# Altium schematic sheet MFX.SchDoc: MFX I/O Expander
size A4; Date: Not used; ApprovedBy: Not used; CheckedBy: Not used; Author: Not used; CompanyName: STMicroelectronics; DrawnBy: Not used; Engineer: Not used; Organization: Not used; Address1: Not used; Address2: Not used; Address3: Not used; Address4: Not used; DocumentNumber: Not used; Revision: Not used; SheetNumber: 18; SheetTotal: 23
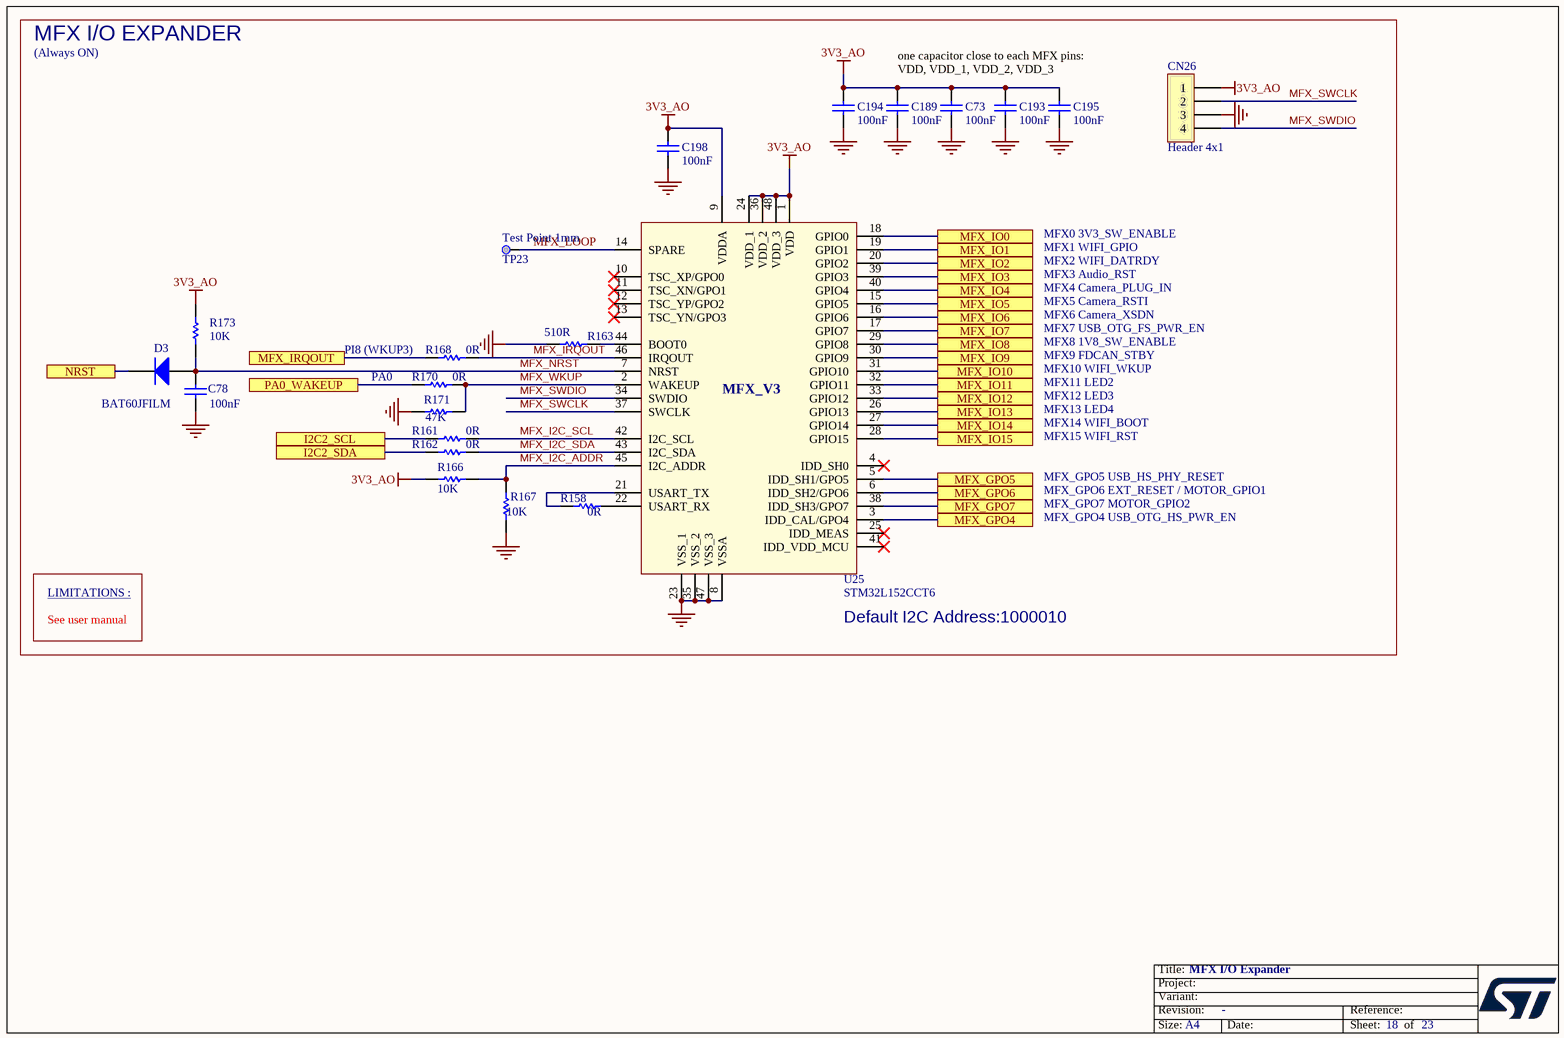
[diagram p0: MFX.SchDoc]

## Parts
C73  value 100nF  [C0402]  (hidden comment: Capacitor)
C78  value 100nF  [C0402]  (hidden comment: Capacitor)
C189  value 100nF  [C0402]  (hidden comment: Capacitor)
C193  value 100nF  [C0402]  (hidden comment: Capacitor)
C194  value 100nF  [C0402]  (hidden comment: Capacitor)
C195  value 100nF  [C0402]  (hidden comment: Capacitor)
C198  value 100nF  [C0402]  (hidden comment: Capacitor)
CN26  Header 4x1  [CON_SAMTEC_TSW-104-07-G-S]
D3  BAT60JFILM  [DIO_SOD323]
R158  value 0R  [R0603]  (hidden comment: Resistor)
R161  value 0R  [R0402]  (hidden comment: Resistor)
R162  value 0R  [R0402]  (hidden comment: Resistor)
R163  value 510R  [R0402]  (hidden comment: Resistor)
R166  value 10K  [R0402]  (hidden comment: Resistor)
R167  value 10K  [R0402]  (hidden comment: Resistor)
R168  value 0R  [R0603]  (hidden comment: Resistor)
R170  value 0R  [R0603]  (hidden comment: Resistor)
R171  value 47K  [R0402]  (hidden comment: Resistor)
R173  value 10K  [R0402]  (hidden comment: Resistor)
TP23  value Test Point 1mm  [TP_SMD_1MM]  (hidden comment: Test Point)  (no BOM)
U25  STM32L152CCT6  [ICC_LQFP48_7X7_P050]

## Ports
I2C2_SCL, I2C2_SDA, MFX_GPO4, MFX_GPO5, MFX_GPO6, MFX_GPO7, MFX_IO0, MFX_IO1, MFX_IO2, MFX_IO3, MFX_IO4, MFX_IO5, MFX_IO6, MFX_IO7, MFX_IO8, MFX_IO9, MFX_IO10, MFX_IO11, MFX_IO12, MFX_IO13, MFX_IO14, MFX_IO15, MFX_IRQOUT, NRST, PA0_WAKEUP

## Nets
3V3_AO: C73.1 C189.2 C193.2 C194.2 C195.2 C198.2 CN26.1 R166.1 R173.2 U25.1(VDD) U25.9(VDDA) U25.24(VDD_1) U25.36(VDD_2) U25.48(VDD_3)
GND: C73.2 C78.1 C189.1 C193.1 C194.1 C195.1 C198.1 CN26.3 R163.2 R167.2 R171.1 U25.8(VSSA) U25.23(VSS_1) U25.35(VSS_2) U25.47(VSS_3)
I2C2_SCL: R161.1 ; port I2C2_SCL
I2C2_SDA: R162.1 ; port I2C2_SDA
MFX_GPO4: U25.3(IDD_CAL/GPO4) ; port MFX_GPO4
MFX_GPO5: U25.5(IDD_SH1/GPO5) ; port MFX_GPO5
MFX_GPO6: U25.6(IDD_SH2/GPO6) ; port MFX_GPO6
MFX_GPO7: U25.38(IDD_SH3/GPO7) ; port MFX_GPO7
MFX_I2C_ADDR: R166.2 R167.1 U25.45(I2C_ADDR)
MFX_I2C_SCL: R161.2 U25.42(I2C_SCL)
MFX_I2C_SDA: R162.2 U25.43(I2C_SDA)
MFX_IO0: U25.18(GPIO0) ; port MFX_IO0
MFX_IO1: U25.19(GPIO1) ; port MFX_IO1
MFX_IO2: U25.20(GPIO2) ; port MFX_IO2
MFX_IO3: U25.39(GPIO3) ; port MFX_IO3
MFX_IO4: U25.40(GPIO4) ; port MFX_IO4
MFX_IO5: U25.15(GPIO5) ; port MFX_IO5
MFX_IO6: U25.16(GPIO6) ; port MFX_IO6
MFX_IO7: U25.17(GPIO7) ; port MFX_IO7
MFX_IO8: U25.29(GPIO8) ; port MFX_IO8
MFX_IO9: U25.30(GPIO9) ; port MFX_IO9
MFX_IO10: U25.31(GPIO10) ; port MFX_IO10
MFX_IO11: U25.32(GPIO11) ; port MFX_IO11
MFX_IO12: U25.33(GPIO12) ; port MFX_IO12
MFX_IO13: U25.26(GPIO13) ; port MFX_IO13
MFX_IO14: U25.27(GPIO14) ; port MFX_IO14
MFX_IO15: U25.28(GPIO15) ; port MFX_IO15
MFX_IRQOUT: R168.2 U25.46(IRQOUT)
MFX_IRQOUT: R168.1 ; port MFX_IRQOUT  [a separate net that carries the same name]
MFX_LOOP: TP23.1 U25.14(SPARE)
MFX_NRST: C78.2 D3.1(A) R173.1 U25.7(NRST)
MFX_SWCLK: CN26.2 U25.37(SWCLK)
MFX_SWDIO: CN26.4 U25.34(SWDIO)
MFX_WKUP: R170.1 R171.2 U25.2(WAKEUP)
NRST: D3.2(K) ; port NRST
PA0_WAKEUP: R170.2 ; port PA0_WAKEUP
NetR158_1: R158.1 U25.21(USART_TX)
NetR158_2: R158.2 U25.22(USART_RX)
NetR163_1: R163.1 U25.44(BOOT0)

Not connected (* = marked no-connect by the designer): U25 4(IDD_SH0)* 10(TSC_XP/GPO0)* 11(TSC_XN/GPO1)* 12(TSC_YP/GPO2)* 13(TSC_YN/GPO3)* 25(IDD_MEAS)* 41(IDD_VDD_MCU)*

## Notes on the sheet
- MFX I/O EXPANDER
- (Always ON)
- one capacitor close to each MFX pins: VDD, VDD_1, VDD_2, VDD_3
- PI8 (WKUP3)
- PA0
- MFX0	3V3_SW_ENABLE
  MFX1	WIFI_GPIO
  MFX2	WIFI_DATRDY
  MFX3	Audio_RST
  MFX4	Camera_PLUG_IN
  MFX5	Camera_RSTI
  MFX6	Camera_XSDN
  MFX7	USB_OTG_FS_PWR_EN
  MFX8	1V8_SW_ENABLE
  MFX9	FDCAN_STBY
  MFX10	WIFI_WKUP
  MFX11	LED2
  MFX12	LED3
  MFX13	LED4
  MFX14	WIFI_BOOT
  MFX15	WIFI_RST
- MFX_GPO5	USB_HS_PHY_RESET
  MFX_GPO6	EXT_RESET / MOTOR_GPIO1
  MFX_GPO7	MOTOR_GPIO2
  MFX_GPO4	USB_OTG_HS_PWR_EN
- LIMITATIONS :
- See user manual
- (near U25) Default I2C Address:1000010

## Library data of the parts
C73 C78 C189 C193-C195 C198 = MCD-00006: Capacitor, MLCC, 100nF, 16V, X7R, 10%, 0402, T=0.5mm; Manufacturer_Part_Number: CC0402KRX7R7BB104; Manufacturer: YAGEO; Alternate_Manufacturer_Part_Number: GCM155R71C104KA55D; Alternate_Manufacturer: MURATA; Part_Preference: Recommended; Partial_Alternate_Internal_Part_Number: MCD-03299; Provided_By: SUBCO; ECCN_US: EAR99; ECCN_EU: NEC; Component_Country_Of_Origin: China; ID: 2474; Order_Code_RS: 9402047; ShowFields: YES
CN26 = MCD-00029: Header, 4x1, 2,54mm, VR, TH, Height 5.84mm/2.54mm; Manufacturer_Part_Number: TSW-104-07-G-S; Manufacturer: SAMTEC; Part_Type: Connector; Part_Preference: Recommended; Provided_By: SUBCO; Component_Country_Of_Origin: China, Costa Rica, Malaysia, USA, Vietnam; ID: 2487; Order_Code_RS: 2667450; ShowFields: YES
D3 = MCD-00034: Manufacturer: STMICROELECTRONICS; Part_Type: Diode; BMS_Part_Number: 9151097; Manufacturer_HQ_COO: EU; Part_Preference: Recommended; Provided_By: SUBCO with ST control; ECCN_US: EAR99; ECCN_EU: NEC; Component_Country_Of_Origin: China; ID: 2483; Order_Code_RS: 714-6879; ShowFields: YES
R158 R168 R170 = MCD-00056: Resistor,0R,0603,5%,1/10W; Manufacturer_Part_Number: RC0603JR-070RL; Manufacturer: YAGEO; Part_Preference: Recommended; Provided_By: SUBCO; ECCN_US: EAR99; ECCN_EU: NEC; Component_Country_Of_Origin: China; ID: 2536; Order_Code_RS: 9233130RL; ShowFields: YES
R161 R162 = MCD-00052: Resistor,0R,0402,5%,1/16W; Manufacturer_Part_Number: RC0402JR-070RL; Manufacturer: YAGEO; Part_Preference: Recommended; Provided_By: SUBCO; ECCN_US: EAR99; ECCN_EU: NEC; Component_Country_Of_Origin: China; ID: 2540; Order_Code_RS: 9232516RL; ShowFields: YES
R163 = MCD-00064: Resistor,510R,0402,1%,1/16W; Manufacturer_Part_Number: RC0402FR-07510RL; Manufacturer: YAGEO; Part_Preference: Recommended; Provided_By: SUBCO; ECCN_US: EAR99; ECCN_EU: NEC; Component_Country_Of_Origin: China; ID: 2525; Order_Code_RS: 1458804; ShowFields: YES
R166 R167 R173 = MCD-00053: Resistor,10K,0402,1%,1/16W; Manufacturer_Part_Number: RC0402FR-0710KL; Manufacturer: YAGEO; BMS_Part_Number: 9131590; Part_Preference: Recommended; Provided_By: SUBCO; ECCN_US: EAR99; ECCN_EU: NEC; Component_Country_Of_Origin: China; ID: 2539; Order_Code_RS: 9239359; ShowFields: YES
R171 = MCD-00063: Resistor,47K,0402,1%,1/16W; Manufacturer_Part_Number: RC0402FR-0747KL; Manufacturer: YAGEO; Part_Preference: Recommended; Provided_By: SUBCO; ECCN_US: EAR99; ECCN_EU: NEC; Component_Country_Of_Origin: China; ID: 2528; Order_Code_RS: 9239430; ShowFields: YES
TP23 = MCD-00074: Test Point 1mm; Part_Type: Misc; Part_Preference: Recommended; Component_Country_Of_Origin: Unknown; ID: 2518; ShowFields: YES
U25 = MCD-00135: Ultra-low-power 32-bit MCU ARM; Manufacturer: STMICROELECTRONICS; Part_Type: IC; BMS_Part_Number: 9175875; Manufacturer_HQ_COO: EU; Part_Preference: Forbidden; Provided_By: SUBCO with ST control; ECCN_US: 3A991A2; ECCN_EU: NEC; Component_Country_Of_Origin: China; ID: 2734; Order_Code_RS: 110-7090; ShowFields: YES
